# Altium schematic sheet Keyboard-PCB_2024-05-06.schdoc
size 349 x 240 mm
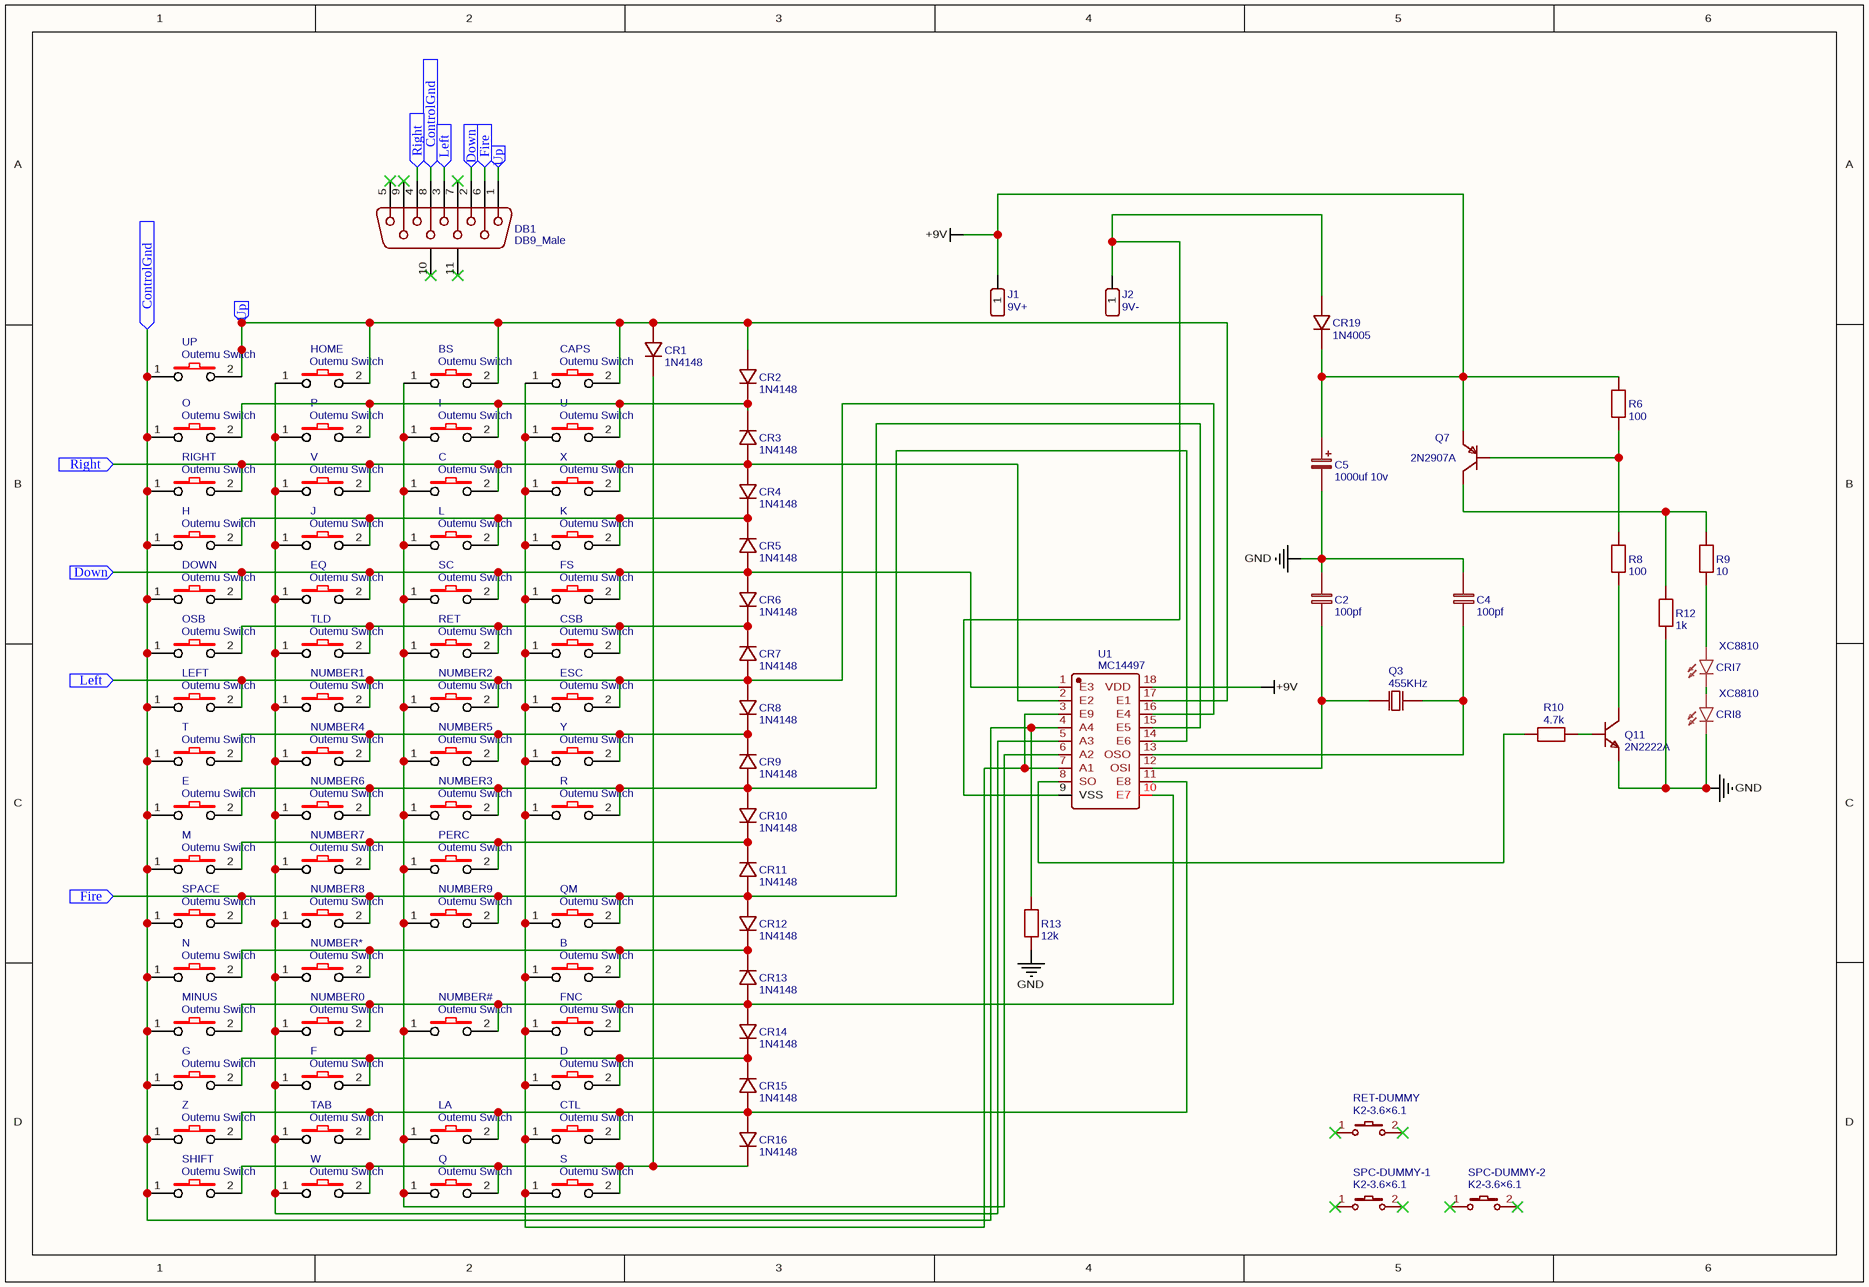
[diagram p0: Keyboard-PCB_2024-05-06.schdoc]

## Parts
B  Outemu Switch  [OUTEMU MX SWITCH FULL BOX]
BS  Outemu Switch  [OUTEMU MX SWITCH FULL BOX]
C  Outemu Switch  [OUTEMU MX SWITCH FULL BOX]
C2  100pf  [RAD-0.2]
C4  100pf  [RAD-0.2]
C5  1000uf 10v  [CAP-D8.0-F3.5]
CAPS  Outemu Switch  [OUTEMU MX SWITCH FULL BOX]
CR1  1N4148  [DO-35_BD2.0-L4.0-P8.00-D0.5-FD]
CR2  1N4148  [DO-35_BD2.0-L4.0-P8.00-D0.5-FD]
CR3  1N4148  [DO-35_BD2.0-L4.0-P8.00-D0.5-FD]
CR4  1N4148  [DO-35_BD2.0-L4.0-P8.00-D0.5-FD]
CR5  1N4148  [DO-35_BD2.0-L4.0-P8.00-D0.5-FD]
CR6  1N4148  [DO-35_BD2.0-L4.0-P8.00-D0.5-FD]
CR7  1N4148  [DO-35_BD2.0-L4.0-P8.00-D0.5-FD]
CR8  1N4148  [DO-35_BD2.0-L4.0-P8.00-D0.5-FD]
CR9  1N4148  [DO-35_BD2.0-L4.0-P8.00-D0.5-FD]
CR10  1N4148  [DO-35_BD2.0-L4.0-P8.00-D0.5-FD]
CR11  1N4148  [DO-35_BD2.0-L4.0-P8.00-D0.5-FD]
CR12  1N4148  [DO-35_BD2.0-L4.0-P8.00-D0.5-FD]
CR13  1N4148  [DO-35_BD2.0-L4.0-P8.00-D0.5-FD]
CR14  1N4148  [DO-35_BD2.0-L4.0-P8.00-D0.5-FD]
CR15  1N4148  [DO-35_BD2.0-L4.0-P8.00-D0.5-FD]
CR16  1N4148  [DO-35_BD2.0-L4.0-P8.00-D0.5-FD]
CR19  1N4005  [DO-41_BD2.4-L4.7-P8.70-D0.9-RD]
CRI7  XC8810  [LTE-302]
CRI8  XC8810  [LTE-302]
CSB  Outemu Switch  [OUTEMU MX SWITCH FULL BOX]
CTL  Outemu Switch  [OUTEMU MX SWITCH FULL BOX]
D  Outemu Switch  [OUTEMU MX SWITCH FULL BOX]
DB1  DB9_Male  [DSUB-TH_DMR-9P]
DOWN  Outemu Switch  [OUTEMU MX SWITCH FULL BOX]
E  Outemu Switch  [OUTEMU MX SWITCH FULL BOX]
EQ  Outemu Switch  [OUTEMU MX SWITCH FULL BOX]
ESC  Outemu Switch  [OUTEMU MX SWITCH FULL BOX]
F  Outemu Switch  [OUTEMU MX SWITCH FULL BOX]
FNC  Outemu Switch  [OUTEMU MX SWITCH FULL BOX]
FS  Outemu Switch  [OUTEMU MX SWITCH FULL BOX]
G  Outemu Switch  [OUTEMU MX SWITCH FULL BOX]
H  Outemu Switch  [OUTEMU MX SWITCH FULL BOX]
HOME  Outemu Switch  [OUTEMU MX SWITCH FULL BOX]
I  Outemu Switch  [OUTEMU MX SWITCH FULL BOX]
J  Outemu Switch  [OUTEMU MX SWITCH FULL BOX]
J1  9V+  [HDR-M-2.54_1X1]
J2  9V-  [HDR-M-2.54_1X1]
K  Outemu Switch  [OUTEMU MX SWITCH FULL BOX]
L  Outemu Switch  [OUTEMU MX SWITCH FULL BOX]
LA  Outemu Switch  [OUTEMU MX SWITCH FULL BOX]
LEFT  Outemu Switch  [OUTEMU MX SWITCH FULL BOX]
M  Outemu Switch  [OUTEMU MX SWITCH FULL BOX]
MINUS  Outemu Switch  [OUTEMU MX SWITCH FULL BOX]
N  Outemu Switch  [OUTEMU MX SWITCH FULL BOX]
NUMBER0  Outemu Switch  [OUTEMU MX SWITCH FULL BOX]
NUMBER1  Outemu Switch  [OUTEMU MX SWITCH FULL BOX]
NUMBER2  Outemu Switch  [OUTEMU MX SWITCH FULL BOX]
NUMBER3  Outemu Switch  [OUTEMU MX SWITCH FULL BOX]
NUMBER4  Outemu Switch  [OUTEMU MX SWITCH FULL BOX]
NUMBER5  Outemu Switch  [OUTEMU MX SWITCH FULL BOX]
NUMBER6  Outemu Switch  [OUTEMU MX SWITCH FULL BOX]
NUMBER7  Outemu Switch  [OUTEMU MX SWITCH FULL BOX]
NUMBER8  Outemu Switch  [OUTEMU MX SWITCH FULL BOX]
NUMBER9  Outemu Switch  [OUTEMU MX SWITCH FULL BOX]
NUMBER#  Outemu Switch  [OUTEMU MX SWITCH FULL BOX]
NUMBER*  Outemu Switch  [OUTEMU MX SWITCH FULL BOX]
O  Outemu Switch  [OUTEMU MX SWITCH FULL BOX]
OSB  Outemu Switch  [OUTEMU MX SWITCH FULL BOX]
P  Outemu Switch  [OUTEMU MX SWITCH FULL BOX]
PERC  Outemu Switch  [OUTEMU MX SWITCH FULL BOX]
Q  Outemu Switch  [OUTEMU MX SWITCH FULL BOX]
Q3  455KHz  [FILTER-TH_2P-L7.0-W3.5-P5.00]
Q7  2N2907A  [TO-92-3_L4.8-W3.7-P2.54-R]
Q11  2N2222A  [TO-92-3_L4.8-W3.7-P2.54-R]
QM  Outemu Switch  [OUTEMU MX SWITCH FULL BOX]
R  Outemu Switch  [OUTEMU MX SWITCH FULL BOX]
R6  100  [R_AXIAL-0.4]
R8  100  [R_AXIAL-0.4]
R9  10  [R_AXIAL-0.4]
R10  4.7k  [R_AXIAL-0.4]
R12  1k  [R_AXIAL-0.4]
R13  12k  [R_AXIAL-0.4]
RET  Outemu Switch  [OUTEMU MX SWITCH FULL BOX]
RET-DUMMY  K2-3.6×6.1  [OUTEMU MX SWITCH FULL BOX]
RIGHT  Outemu Switch  [OUTEMU MX SWITCH FULL BOX]
S  Outemu Switch  [OUTEMU MX SWITCH FULL BOX]
SC  Outemu Switch  [OUTEMU MX SWITCH FULL BOX]
SHIFT  Outemu Switch  [OUTEMU MX SWITCH FULL BOX]
SPACE  Outemu Switch  [OUTEMU MX SWITCH FULL BOX]
SPC-DUMMY-1  K2-3.6×6.1  [OUTEMU MX SWITCH FULL BOX]
SPC-DUMMY-2  K2-3.6×6.1  [OUTEMU MX SWITCH FULL BOX]
T  Outemu Switch  [OUTEMU MX SWITCH FULL BOX]
TAB  Outemu Switch  [OUTEMU MX SWITCH FULL BOX]
TLD  Outemu Switch  [OUTEMU MX SWITCH FULL BOX]
U  Outemu Switch  [OUTEMU MX SWITCH FULL BOX]
U1  MC14497  [DIP-18_L23.0-W6.5-P2.54-LS7.6-BL]
UP  Outemu Switch  [OUTEMU MX SWITCH FULL BOX]
V  Outemu Switch  [OUTEMU MX SWITCH FULL BOX]
W  Outemu Switch  [OUTEMU MX SWITCH FULL BOX]
X  Outemu Switch  [OUTEMU MX SWITCH FULL BOX]
Y  Outemu Switch  [OUTEMU MX SWITCH FULL BOX]
Z  Outemu Switch  [OUTEMU MX SWITCH FULL BOX]

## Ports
ControlGnd (in), Down (in), Fire (in), Left (in), Right (in), Up (in)

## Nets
+9V: C5.1 CR19.1 J1.1 Q7.3(E) R6.1 U1.18(VDD)
GND: C2.1 C4.1 C5.2 CRI8.C Q11.3(E) R12.2 R13.2
ControlGnd: DB1.8 DOWN.1 E.1 G.1 H.1 LEFT.1 M.1 MINUS.1 N.1 O.1 OSB.1 R13.1 RIGHT.1 SHIFT.1 SPACE.1 T.1 U1.4(A4) UP.1 Z.1 ; port ControlGnd
Down: CR5.1 CR6.1 DB1.2 DOWN.2 EQ.2 FS.2 SC.2 U1.1(E3) ; port Down
Fire: CR11.1 CR12.1 DB1.6 NUMBER8.2 NUMBER9.2 QM.2 SPACE.2 U1.14(E6) ; port Fire
Left: CR7.1 CR8.1 DB1.3 ESC.2 LEFT.2 NUMBER1.2 NUMBER2.2 U1.16(E4) ; port Left
Right: C.2 CR3.1 CR4.1 DB1.4 RIGHT.2 U1.2(E2) V.2 X.2 ; port Right
Up: BS.2 CAPS.2 CR1.1 CR2.1 DB1.1 HOME.2 U1.17(E1) UP.2 ; port Up
NetB_1: B.1 CAPS.1 CSB.1 CTL.1 D.1 ESC.1 FNC.1 FS.1 K.1 QM.1 R.1 S.1 U.1 U1.3(E9) U1.7(A1) X.1 Y.1
NetB_2: B.2 CR12.2 CR13.2 N.2 NUMBER*.2
NetBS_1: BS.1 C.1 I.1 L.1 LA.1 NUMBER2.1 NUMBER3.1 NUMBER5.1 NUMBER9.1 NUMBER#.1 PERC.1 Q.1 RET.1 SC.1 U1.6(A2)
NetC2_2: C2.2 Q3.2(OSC2) U1.12(OSI)
NetC4_2: C4.2 Q3.1(OSC1) U1.13(OSO)
NetCR1_2: CR1.2 CR16.2 Q.2 S.2 SHIFT.2 W.2
NetCR2_2: CR2.2 CR3.2 I.2 O.2 P.2 U.2
NetCR4_2: CR4.2 CR5.2 H.2 J.2 K.2 L.2
NetCR6_2: CR6.2 CR7.2 CSB.2 OSB.2 RET.2 TLD.2
NetCR8_2: CR8.2 CR9.2 NUMBER4.2 NUMBER5.2 T.2 Y.2
NetCR9_1: CR9.1 CR10.1 E.2 NUMBER3.2 NUMBER6.2 R.2 U1.15(E5)
NetCR10_2: CR10.2 CR11.2 M.2 NUMBER7.2 PERC.2
NetCR13_1: CR13.1 CR14.1 FNC.2 MINUS.2 NUMBER0.2 NUMBER#.2 U1.10(E7)
NetCR14_2: CR14.2 CR15.2 D.2 F.2 G.2
NetCR15_1: CR15.1 CR16.1 CTL.2 LA.2 TAB.2 U1.11(E8) Z.2
NetCR19_2: CR19.2 J2.1 U1.9(VSS)
NetCRI7_A: CRI7.A R9.2
NetCRI7_C: CRI7.C CRI8.A
NetEQ_1: EQ.1 F.1 HOME.1 J.1 NUMBER0.1 NUMBER1.1 NUMBER4.1 NUMBER6.1 NUMBER7.1 NUMBER8.1 NUMBER*.1 P.1 TAB.1 TLD.1 U1.5(A3) V.1 W.1
NetQ7_1: Q7.1(C) R9.1 R12.1
NetQ7_2: Q7.2(B) R6.2 R8.1
NetQ11_1: Q11.1(C) R8.2
NetQ11_2: Q11.2(B) R10.1
NetR10_2: R10.2 U1.8(SO)

Not connected (* = marked no-connect by the designer): DB1 5* 7* 9* 10(MH1)* 11(MH2)*; RET-DUMMY 1* 2*; SPC-DUMMY-1 1* 2*; SPC-DUMMY-2 1* 2*

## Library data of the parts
B BS C CAPS CSB CTL D DOWN E EQ ESC F FNC FS G H HOME I J K L LA LEFT M MINUS N NUMBER0-NUMBER9 NUMBER# NUMBER* O OSB P PERC Q QM R RET RIGHT S SC SHIFT SPACE T TAB TLD U UP V W X Y Z = Outemu Switch: Contributor: Ravi Shankar
C2 C4 = 100pf: nameAlias: Value(F); Contributor: LCEDA_Lib
C5 = 1000uf 10v: nameAlias: Value(F); Contributor: LCEDA_Lib
CR1-CR16 = 1N4148: Manufacturer: SEMTECH; Contributor: LCEDA_Lib
CR19 = 1N4005: Manufacturer: SEMTECH; Manufacturer Part: 1N4007; Contributor: LCEDA_Lib
CRI7 CRI8 = XC8810: Contributor: A.E Components
DB1 = DB9_Male: Manufacturer: Amphenol; Contributor: LCEDA_Lib
J1 = 9V+: Contributor: LCEDA_Lib
J2 = 9V-: Contributor: LCEDA_Lib
Q3 = 455KHz: Manufacturer: KYX; Manufacturer Part: KCR455E; nameAlias: Value; Contributor: LCSC
Q7 = 2N2907A: Manufacturer: Foshan Blue Rocket Elec; Contributor: LCSC
Q11 = 2N2222A: Manufacturer: Foshan Blue Rocket Elec; Contributor: LCSC
R6 R8 = 100: nameAlias: Value(Ω); Contributor: LCEDA_Lib
R9 = 10: nameAlias: Value(Ω); Contributor: LCEDA_Lib
R10 = 4.7k: nameAlias: Value(Ω); Contributor: LCEDA_Lib
R12 = 1k: nameAlias: Value(Ω); Contributor: LCEDA_Lib
R13 = 12k: nameAlias: Value(Ω); Contributor: LCEDA_Lib
RET-DUMMY SPC-DUMMY-1 SPC-DUMMY-2 = K2-3.6×6.1: Manufacturer Part: K2-1107ST-A4SW-06; Contributor: LCEDA_Lib; 制造商: 韩国韩荣
U1 = MC14497: Manufacturer: MOTOROLA; Manufacturer Part: MC14497P; Contributor: jonn.blanchard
